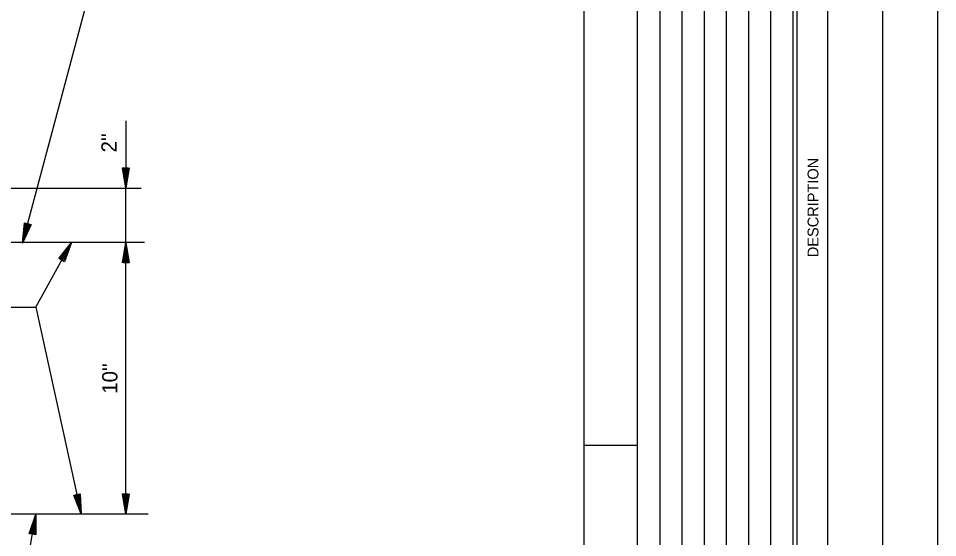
# Model space of a CAD drawing. Extents: x 22369.6 to 22428.3, y 22369.6 to 22415.
# Drawn here: x 22417.01 to 22428.29, y 22402.17 to 22408.53 of the extents above; entities that cross this region are included whole.
import ezdxf

# ---------------------------------------------------------------- set-up
doc = ezdxf.new("R2010")
doc.units = 0
for name, color, linetype in [('Level 1', 7, 'Continuous'), ('Level 10', 7, 'Continuous'), ('Level 2', 7, 'Continuous'), ('Level 4', 7, 'Continuous'), ('Level 9', 7, 'Continuous')]:
    doc.layers.add(name, color=color, linetype=linetype)

msp = doc.modelspace()

# ---------------------------------------------------------------- linework, layer by layer
at = {"layer": 'Level 1'}
for p, q in [((22424.88, 22411.461), (22424.88, 22391.461)), ((22425.152, 22411.461), (22425.152, 22391.461)), ((22425.424, 22411.461), (22425.424, 22391.461)), ((22425.696, 22411.461), (22425.696, 22391.461)), ((22425.968, 22411.461), (22425.968, 22391.461)), ((22426.24, 22411.461), (22426.24, 22391.461)), ((22426.512, 22411.461), (22426.512, 22391.461)), ((22426.56, 22411.461), (22426.56, 22391.461)), ((22417.067, 22405.776), (22418.494, 22411.144)), ((22418.332, 22407.277), (22418.332, 22406.453)), ((22418.332, 22406.522), (22418.332, 22406.522)), ((22412.529, 22406.453), (22418.521, 22406.453)), ((22418.332, 22405.786), (22418.332, 22406.453)), ((22418.332, 22406.453), (22418.332, 22406.453)), ((22417.085, 22405.843), (22417.085, 22405.843)), ((22418.563, 22405.786), (22411.998, 22405.786)), ((22417.067, 22405.776), (22417.067, 22405.776)), ((22417.228, 22404.991), (22417.667, 22405.786)), ((22417.633, 22405.725), (22417.633, 22405.725)), ((22417.667, 22405.786), (22417.667, 22405.786)), ((22418.332, 22405.786), (22418.332, 22405.786)), ((22418.332, 22402.453), (22418.332, 22405.786)), ((22418.332, 22405.717), (22418.332, 22405.717)), ((22416.683, 22404.991), (22417.228, 22404.991)), ((22417.228, 22404.991), (22417.786, 22402.453)), ((22418.606, 22402.453), (22411.998, 22402.453)), ((22416.028, 22395.738), (22417.23, 22402.453)), ((22417.23, 22402.453), (22417.23, 22402.453)), ((22417.772, 22402.52), (22417.772, 22402.52)), ((22417.786, 22402.453), (22417.786, 22402.453)), ((22418.332, 22402.522), (22418.332, 22402.522)), ((22418.332, 22402.453), (22418.332, 22402.453))]:
    msp.add_line(p, q, dxfattribs=at)
msp.add_lwpolyline([(22369.621, 22414.965), (22428.288, 22414.965), (22428.288, 22369.621), (22369.621, 22369.621)], close=True, dxfattribs=at)
for points in [[(22424.608, 22391.711), (22424.608, 22411.211)], [(22426.944, 22391.711), (22426.944, 22411.211)], [(22418.373, 22406.702), (22418.332, 22406.453), (22418.29, 22406.702), (22418.361, 22406.702), (22418.332, 22406.522), (22418.304, 22406.691), (22418.349, 22406.691), (22418.332, 22406.589), (22418.317, 22406.681), (22418.336, 22406.681), (22418.332, 22406.658)], [(22417.171, 22406.007), (22417.067, 22405.776), (22417.091, 22406.028), (22417.16, 22406.01), (22417.085, 22405.843), (22417.102, 22406.014), (22417.145, 22406.003), (22417.102, 22405.908), (22417.112, 22406), (22417.13, 22405.996), (22417.12, 22405.975)], [(22417.51, 22405.588), (22417.667, 22405.786), (22417.582, 22405.548), (22417.521, 22405.582), (22417.633, 22405.725), (22417.576, 22405.564), (22417.536, 22405.585), (22417.601, 22405.667), (22417.569, 22405.579), (22417.553, 22405.588), (22417.567, 22405.606)], [(22418.29, 22405.537), (22418.332, 22405.786), (22418.373, 22405.537), (22418.302, 22405.537), (22418.332, 22405.717), (22418.36, 22405.547), (22418.314, 22405.547), (22418.332, 22405.65), (22418.346, 22405.558), (22418.328, 22405.558), (22418.332, 22405.581)], [(22417.773, 22402.705), (22417.786, 22402.453), (22417.693, 22402.687), (22417.762, 22402.703), (22417.772, 22402.52), (22417.708, 22402.68), (22417.752, 22402.69), (22417.757, 22402.586), (22417.723, 22402.672), (22417.741, 22402.676), (22417.742, 22402.653)], [(22418.373, 22402.702), (22418.332, 22402.453), (22418.29, 22402.702), (22418.361, 22402.702), (22418.332, 22402.522), (22418.304, 22402.691), (22418.349, 22402.691), (22418.332, 22402.589), (22418.317, 22402.681), (22418.336, 22402.681), (22418.332, 22402.658)], [(22417.145, 22402.215), (22417.23, 22402.453), (22417.227, 22402.2), (22417.157, 22402.212), (22417.218, 22402.384), (22417.215, 22402.213), (22417.171, 22402.221), (22417.206, 22402.319), (22417.204, 22402.226), (22417.186, 22402.229), (22417.194, 22402.251)]]:
    msp.add_lwpolyline(points, dxfattribs=at)
at = {"layer": 'Level 10'}
msp.add_line((22423.952, 22403.301), (22424.608, 22403.301), dxfattribs=at)
at = {"layer": 'Level 2'}
msp.add_line((22417.218, 22402.384), (22417.218, 22402.384), dxfattribs=at)
at = {"layer": 'Level 9'}
msp.add_line((22427.616, 22370.293), (22427.616, 22414.293), dxfattribs=at)
msp.add_lwpolyline([(22423.952, 22370.293), (22423.952, 22414.293)], dxfattribs=at)

# ---------------------------------------------------------------- texts
at = {"layer": 'Level 1'}
msp.add_text('DESCRIPTION', height=0.13333, rotation=90, dxfattribs=at).set_placement((22426.827, 22405.605))
at = {"layer": 'Level 4'}
for s, p in [("2''", (22418.219, 22406.89)), ("10''", (22418.229, 22403.931))]:
    msp.add_text(s, height=0.1867, rotation=90, dxfattribs=at).set_placement(p)

doc.saveas('drawing.dxf')
